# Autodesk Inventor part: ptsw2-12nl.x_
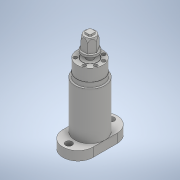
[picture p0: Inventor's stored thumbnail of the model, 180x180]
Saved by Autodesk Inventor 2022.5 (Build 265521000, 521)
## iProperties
Part Number: ptsw2-12nl.x_
Material: 一般
Document SubType Name: Modeling
Designer: ImaoCorp
Density: 1 g/cm^3
Appearance: 既定
Sending System: SOLIDWORKS 2017-2017317
MC: AMD64
MC_MODEL: Intel64 Family 6 Model 60 Stepping 3, GenuineIntel
OS: Windows_NT
FRU: Parasolid Version 29.0, build 201,  4-17-2017
FORMAT: text
GUISE: transmit
KEY: ptsw2-12nl
FILE: ptsw2-12nl.x_t
DATE: Wed Sep 04 15:22:22 2019
Author: ImaoCorp
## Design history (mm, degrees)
feature "Base1"
node "ソリッド1"
